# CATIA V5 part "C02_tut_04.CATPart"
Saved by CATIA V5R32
Part number: Part1
Bounding box of the stored display mesh (mm): x 0 to 60, y -30 to 120, z -50 to 25
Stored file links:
  D:\PROJECTS\Project 2022\CATIA V5 6R 2022\Resources\Tutorial Files\c02_catia_v5_6r2022_tut\C02_tut_04.CATPart
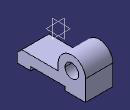
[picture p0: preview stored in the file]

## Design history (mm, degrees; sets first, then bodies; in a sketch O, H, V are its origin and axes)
Body1 (main body)
  Sketch1 on yz-plane, origin (0, 0, 0), H (0, 1, 0), V (0, 0, 1)
    line L1 (-30, -50) -> (0, -50)
    point P1 (0, -50)
    point P2 (-30, -50)
    line L2 (0, -50) -> (0, -42)
    line L3 (0, -42) -> (75, -42)
    line L4 (75, -42) -> (75, -50)
    line L5 (75, -50) -> (120, -50)
    line L6 (120, -50) -> (120, -5)
    arc A1 centre (90, -5) radius 30 from (120, -5) to (60, -5) ccw
    line L7 (60, -5) -> (60, -20)
    line L8 (60, -20) -> (-20, -20)
    point P11 (-20, -20)
    line L9 (-20, -20) -> (-30, -30)
    point P12 (-30, -30)
    line L10 (-30, -30) -> (-30, -50)
    point P13 (-30, -50)
    circle A2 centre (90, -5) radius 15
    length L2 = 8
    length L3 = 75
    radius A1 = 30
    angle L9 H = 225
    distance P11 P12 H = 10
    length L10 = 20
    radius A2 = 15
    coincidence: P1 V, P13 L1, P2 P13
    horizontal: L1 H, L3 H, L5 H, L8 H
    vertical: L4 V, L6 V, L10 V
    tangency: A1 L6, L7 A1, A2 L8
  Pad1: profile Sketch1, direction (1, 0, 0), length 60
